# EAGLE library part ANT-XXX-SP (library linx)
ANT-315-SP Source: http://www.antennafactor.com/documents/ANT-315-SP_Data_Sheet.pdf
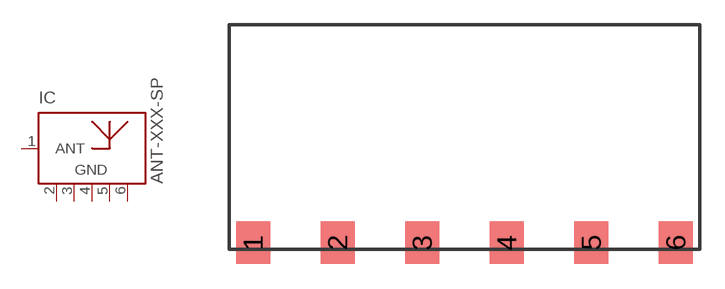
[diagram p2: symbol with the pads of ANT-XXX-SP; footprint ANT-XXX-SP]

Designator prefix IC

## ANT-XXX-SP  [ANT-XXX-SP]
1  ANT  pas
2  GND  pas
3  GND  pas
4  GND  pas
5  GND  pas
6  GND  pas

## Footprint ANT-XXX-SP (pad centres in mm)
ANT-xxx-SP Source: All Packages.pdf
smd 2.032 x 2.54: 1 -12.7,0; 2 -7.62,0; 3 -2.54,0; 4 2.54,0; 5 7.62,0; 6 12.7,0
